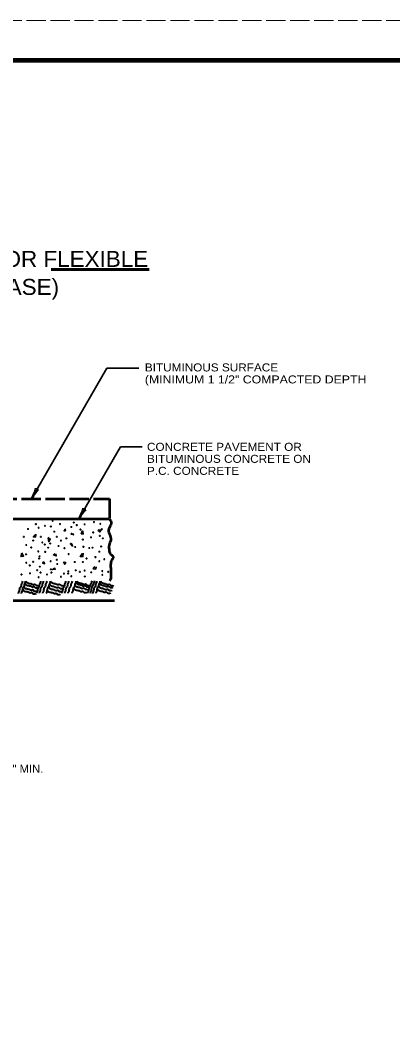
# Model space of a CAD drawing. Extents: x -488 to 193, y 19 to 459.
# Drawn here: x -135 to -41.9, y 203.1 to 458.9 of the extents above; entities that cross this region are included whole.
import ezdxf
from ezdxf.enums import TextEntityAlignment as Align

# ---------------------------------------------------------------- set-up
doc = ezdxf.new("R2010")
doc.units = 0
doc.header["$LTSCALE"] = 0.8
doc.linetypes.add('LONG_DASHED', pattern=[7.5, 6, -1.5])
doc.layers.add('1', color=7, linetype='Continuous', lineweight=40)
doc.layers.add('61', color=7, linetype='Continuous', lineweight=35)

msp = doc.modelspace()

# ---------------------------------------------------------------- linework, layer by layer
at = {"layer": '1', "lineweight": 60}
msp.add_line((-127.368, 396.6702), (-102.8286, 396.6702), dxfattribs=at)
at = {"layer": '1', "lineweight": 35}
for p, q in [((-132.2735, 339.2816), (-113.4017, 371.9683)), ((-113.4017, 371.9683), (-105.4017, 371.9683)), ((-120.4165, 334.2816), (-110.0276, 352.2757)), ((-110.0276, 352.2757), (-104.5276, 352.2757))]:
    msp.add_line(p, q, dxfattribs=at)
at = {"layer": '1', "linetype": 'LONG_DASHED', "lineweight": 53}
for p, q in [((-272.7425, 339.2816), (-112.7425, 339.2816)), ((-112.7425, 339.2816), (-112.7425, 334.2816))]:
    msp.add_line(p, q, dxfattribs=at)
at = {"layer": '1', "lineweight": 53}
for p, q in [((-272.7425, 334.2816), (-112.7425, 334.2816)), ((-271.5283, 313.9212), (-111.5283, 313.9212))]:
    msp.add_line(p, q, dxfattribs=at)
at = {"layer": '1', "lineweight": 35}
for points in [[(-131.3389, 330.2921), (-131.7698, 329.7996), (-131.2774, 329.7381), (-131.1542, 330.4767)], [(-123.7057, 331.7695), (-124.1366, 331.3386), (-123.7672, 331.3386), (-123.8904, 331.7695)], [(-119.4582, 331.4002), (-119.8275, 330.5998), (-119.3351, 330.4767), (-119.3966, 331.277)], [(-115.2722, 331.6463), (-115.58, 331.4002), (-115.1491, 331.0308), (-114.9028, 331.4002), (-115.0875, 331.6463)], [(-128.0763, 329.4918), (-127.9532, 328.5684), (-127.5839, 329.2456), (-128.1379, 329.6765)], [(-122.5977, 328.1375), (-121.9821, 327.4604), (-122.1667, 328.0144), (-122.4745, 328.2607)], [(-134.7247, 325.6752), (-134.8478, 324.8749), (-134.2322, 324.9981), (-134.6632, 325.7983)], [(-126.4142, 325.6752), (-126.7837, 325.3058), (-126.0449, 325.0596), (-126.1681, 325.5521)], [(-119.4582, 325.6752), (-120.0737, 324.8749), (-119.3966, 324.8749), (-119.3351, 325.7367)], [(-129.1844, 323.5822), (-129.4922, 323.2744), (-128.9998, 323.0897), (-129.1228, 323.5207)], [(-124.2597, 323.5207), (-123.9519, 322.9666), (-123.7057, 323.3975), (-124.2597, 323.4591)], [(-116.3802, 322.4126), (-116.8112, 321.797), (-116.1956, 321.7354), (-116.0724, 322.2895)], [(-126.6688, 321.9947), (-127.0382, 321.6253), (-126.2995, 321.6869), (-126.5457, 322.0562)]]:
    msp.add_lwpolyline(points, dxfattribs=at)
for centre in [(-131.1542, 333.0007), (-128.8766, 332.5697), (-127.3992, 332.3851), (-126.9683, 333.8009), (-125.1216, 333.0007), (-121.6743, 333.37), (-120.9356, 332.7544), (-118.9657, 332.9391), (-116.6265, 333.4931), (-115.0259, 333.0623), (-133.1242, 331.7695), (-130.4772, 332.0772), (-126.5374, 331.0923), (-122.2898, 332.2619), (-122.2283, 330.5383), (-121.7974, 330.4152), (-120.0122, 331.6463), (-116.8112, 330.9077), (-115.1491, 330.0458), (-114.6566, 331.7079), (-134.1707, 329.7996), (-133.5551, 327.7682), (-131.8314, 328.8762), (-129.9231, 329.7996), (-129.5538, 328.3837), (-128.9382, 327.8913), (-127.5839, 328.1375), (-125.9218, 329.7996), (-125.4909, 327.5219), (-124.8753, 328.8762), (-123.521, 329.4303), (-121.3049, 327.2758), (-119.3966, 329.1225), (-119.2735, 327.3372), (-117.3652, 329.6765), (-114.8413, 327.3988), (-114.4103, 329.4303), (-133.6167, 325.4289), (-132.3239, 327.1526), (-130.5387, 326.1677), (-130.2309, 324.9365), (-128.8151, 326.0445), (-128.0763, 327.091), (-124.0135, 326.9679), (-122.967, 325.4905), (-117.7961, 327.0295), (-116.9958, 327.091), (-116.2571, 324.7518), (-115.2722, 326.1061), (-133.5551, 323.336), (-132.6933, 322.6588), (-131.8314, 323.5822), (-130.354, 324.3824), (-130.1693, 322.351), (-127.4607, 323.7053), (-125.9218, 324.0747), (-125.7987, 323.0282), (-121.428, 323.5207), (-119.3966, 323.5207), (-118.4732, 324.3824), (-115.2722, 323.7053), (-114.041, 324.1977), (-134.7862, 320.3812), (-132.6317, 320.6889), (-130.8465, 321.4892), (-130.4772, 319.704), (-129.9847, 320.8736), (-128.3842, 320.3812), (-127.3992, 321.6739), (-127.2761, 320.8736), (-124.8753, 319.8272), (-124.1366, 320.6274), (-123.0901, 320.6274), (-123.0286, 321.1814), (-122.2898, 319.9502), (-121.1818, 321.4277), (-120.1353, 321.0583), (-118.9657, 321.3661), (-118.9042, 319.8887), (-117.3036, 320.9352), (-114.5335, 321.243), (-114.5335, 320.3196), (-113.0561, 321.0583)]:
    msp.add_circle(centre, 0.1, dxfattribs=at)
at = {"layer": '1'}
for centre, major_axis, ratio, start_param, end_param in [((-131.9672, 340.3647), (-0.7576, -1.6245), 0.122415, 0.89635335, 3.14159265), ((-131.9672, 340.3647), (-0.7576, -1.6245), 0.122415, 0.89635335, 3.14159265), ((-131.53, 340.1462), (1.0303, 1.4333), 0.07063, 6.28230741, 8.55970261), ((-131.53, 340.1462), (1.0303, 1.4333), 0.07063, 6.28230741, 8.55970261), ((-120.1102, 335.3647), (-0.7576, -1.6245), 0.122415, 0.89635335, 3.14159265), ((-119.673, 335.1462), (-1.0303, -1.4333), 0.07063, 3.14071475, 5.41810995)]:
    msp.add_ellipse(centre, major_axis=major_axis, ratio=ratio, start_param=start_param, end_param=end_param, dxfattribs=at)
at = {"layer": '1', "lineweight": 53}
msp.add_spline([(-112.7425, 334.2816), (-112.2962, 333.2177), (-112.9979, 331.3631), (-112.7472, 330.4608), (-112.4465, 329.0072), (-112.8475, 327.7542), (-112.7974, 326.3006), (-112.647, 325.7492), (-111.845, 324.847), (-112.2962, 323.6941), (-112.4465, 323.1427), (-112.4465, 321.9899), (-112.3964, 320.9874), (-112.4465, 320.1353), (-112.4465, 319.3834), (-112.7425, 318.7816)], degree=3, dxfattribs=at)
at = {"layer": '1'}
for points in [[(-134.5498, 318.7058), (-134.6353, 318.2209), (-134.8207, 317.8786), (-134.9276, 317.2722), (-135.2343, 316.9513), (-135.2556, 316.8302), (-135.3197, 316.4663), (-135.3838, 316.1026), (-135.5693, 315.7603), (-135.5907, 315.639)], [(-133.8112, 318.7058), (-133.8967, 318.2209), (-134.082, 317.8786), (-134.1889, 317.2722), (-134.4957, 316.9513), (-134.5169, 316.8302), (-134.5811, 316.4663), (-134.6452, 316.1026), (-134.8307, 315.7603), (-134.8521, 315.639)], [(-134.2132, 317.3456), (-133.9203, 317.012), (-133.0878, 316.789), (-132.85, 316.7253), (-132.1365, 316.5341), (-131.9857, 316.6212), (-131.5736, 316.2559), (-131.0662, 316.2473), (-130.9791, 316.0966)], [(-133.9054, 318.1458), (-133.6125, 317.8123), (-132.78, 317.5892), (-132.5422, 317.5256), (-131.8287, 317.3343), (-131.6778, 317.4214), (-131.2657, 317.0562), (-130.7583, 317.0475), (-130.6712, 316.8968)], [(-133.6592, 318.6999), (-133.3663, 318.3663), (-132.5337, 318.1433), (-132.2959, 318.0797), (-131.5824, 317.8884), (-131.4316, 317.9755), (-131.0195, 317.6103), (-130.5121, 317.6016), (-130.425, 317.4509)], [(-129.9945, 318.7674), (-130.08, 318.2825), (-130.2653, 317.9402), (-130.3723, 317.3338), (-130.679, 317.0129), (-130.7002, 316.8918), (-130.7644, 316.5279), (-130.8285, 316.1642), (-131.014, 315.8219), (-131.0354, 315.7006)], [(-129.3173, 318.7674), (-129.4028, 318.2825), (-129.5882, 317.9402), (-129.6951, 317.3338), (-130.0018, 317.0129), (-130.0231, 316.8918), (-130.0872, 316.5279), (-130.1513, 316.1642), (-130.3368, 315.8219), (-130.3582, 315.7006)], [(-128.4555, 318.7674), (-128.541, 318.2825), (-128.7263, 317.9402), (-128.8332, 317.3338), (-129.14, 317.0129), (-129.1612, 316.8918), (-129.2254, 316.5279), (-129.2895, 316.1642), (-129.475, 315.8219), (-129.4964, 315.7006)], [(-127.5937, 318.7058), (-127.6792, 318.2209), (-127.8645, 317.8786), (-127.9714, 317.2722), (-128.2782, 316.9513), (-128.2994, 316.8302), (-128.3636, 316.4663), (-128.4277, 316.1026), (-128.6132, 315.7603), (-128.6346, 315.639)], [(-127.9342, 317.2225), (-127.6413, 316.8889), (-126.8088, 316.6659), (-126.571, 316.6022), (-125.8575, 316.411), (-125.7067, 316.4981), (-125.2946, 316.1328), (-124.7872, 316.1242), (-124.7001, 315.9735)], [(-127.7496, 317.9612), (-127.4567, 317.6276), (-126.6242, 317.4046), (-126.3863, 317.3409), (-125.6728, 317.1497), (-125.522, 317.2367), (-125.1099, 316.8715), (-124.6025, 316.8628), (-124.5154, 316.7122)], [(-127.5033, 318.6999), (-127.2104, 318.3663), (-126.3779, 318.1433), (-126.1401, 318.0797), (-125.4266, 317.8884), (-125.2758, 317.9755), (-124.8637, 317.6103), (-124.3563, 317.6016), (-124.2692, 317.4509)], [(-123.7155, 318.7674), (-123.801, 318.2825), (-123.9863, 317.9402), (-124.0932, 317.3338), (-124.4, 317.0129), (-124.4213, 316.8918), (-124.4854, 316.5279), (-124.5495, 316.1642), (-124.735, 315.8219), (-124.7564, 315.7006)], [(-122.9767, 318.7674), (-123.0622, 318.2825), (-123.2476, 317.9402), (-123.3545, 317.3338), (-123.6612, 317.0129), (-123.6825, 316.8918), (-123.7467, 316.5279), (-123.8107, 316.1642), (-123.9962, 315.8219), (-124.0177, 315.7006)], [(-122.1149, 318.7674), (-122.2004, 318.2825), (-122.3858, 317.9402), (-122.4927, 317.3338), (-122.7994, 317.0129), (-122.8207, 316.8918), (-122.8848, 316.5279), (-122.9489, 316.1642), (-123.1344, 315.8219), (-123.1558, 315.7006)], [(-121.13, 318.7674), (-121.2155, 318.2825), (-121.4008, 317.9402), (-121.5078, 317.3338), (-121.8145, 317.0129), (-121.8357, 316.8918), (-121.8999, 316.5279), (-121.964, 316.1642), (-122.1495, 315.8219), (-122.1709, 315.7006)], [(-121.4706, 317.7765), (-121.1777, 317.4429), (-120.3452, 317.2199), (-120.1073, 317.1562), (-119.3938, 316.965), (-119.243, 317.0521), (-118.8309, 316.6868), (-118.3235, 316.6782), (-118.2364, 316.5275)], [(-121.1628, 318.3921), (-120.8699, 318.0585), (-120.0374, 317.8355), (-119.7996, 317.7718), (-119.0861, 317.5806), (-118.9352, 317.6677), (-118.5232, 317.3024), (-118.0157, 317.2937), (-117.9287, 317.1431)], [(-120.9166, 318.7615), (-120.6237, 318.4279), (-119.7912, 318.2049), (-119.5533, 318.1413), (-118.8398, 317.95), (-118.689, 318.0371), (-118.2769, 317.6718), (-117.7695, 317.6632), (-117.6824, 317.5125)], [(-117.1903, 318.829), (-117.2758, 318.3441), (-117.4612, 318.0018), (-117.5681, 317.3954), (-117.8748, 317.0745), (-117.8961, 316.9533), (-117.9603, 316.5895), (-118.0243, 316.2258), (-118.2098, 315.8835), (-118.2313, 315.7622)], [(-116.5747, 318.829), (-116.6602, 318.3441), (-116.8456, 318.0018), (-116.9525, 317.3954), (-117.2592, 317.0745), (-117.2805, 316.9533), (-117.3447, 316.5895), (-117.4087, 316.2258), (-117.5943, 315.8835), (-117.6157, 315.7622)], [(-115.9592, 318.7058), (-116.0447, 318.2209), (-116.23, 317.8786), (-116.3369, 317.2722), (-116.6437, 316.9513), (-116.6649, 316.8302), (-116.7291, 316.4663), (-116.7932, 316.1026), (-116.9787, 315.7603), (-117.0001, 315.639)], [(-115.1589, 318.7674), (-115.2444, 318.2825), (-115.4297, 317.9402), (-115.5367, 317.3338), (-115.8434, 317.0129), (-115.8647, 316.8918), (-115.9288, 316.5279), (-115.9929, 316.1642), (-116.1784, 315.8219), (-116.1998, 315.7006)], [(-115.4378, 317.4688), (-115.1449, 317.1352), (-114.3124, 316.9122), (-114.0746, 316.8485), (-113.3611, 316.6572), (-113.2103, 316.7443), (-112.7982, 316.3791), (-112.2908, 316.3704), (-112.2037, 316.2197)], [(-115.2532, 318.2074), (-114.9603, 317.8738), (-114.1277, 317.6508), (-113.8899, 317.5872), (-113.1764, 317.3959), (-113.0256, 317.483), (-112.6135, 317.1178), (-112.1061, 317.1091), (-112.019, 316.9584)], [(-115.0069, 318.6999), (-114.714, 318.3663), (-113.8815, 318.1433), (-113.6437, 318.0797), (-112.9302, 317.8884), (-112.7793, 317.9755), (-112.3672, 317.6103), (-111.8598, 317.6016), (-111.7728, 317.4509)], [(-134.4595, 316.6684), (-134.1666, 316.3348), (-133.3341, 316.1118), (-133.0962, 316.0482), (-132.3827, 315.8569), (-132.2319, 315.944), (-131.8198, 315.5788), (-131.3124, 315.5701), (-131.2253, 315.4194)], [(-128.3652, 316.4837), (-128.0722, 316.1502), (-127.2398, 315.9272), (-127.0019, 315.8635), (-126.2884, 315.6722), (-126.1376, 315.7593), (-125.7255, 315.3941), (-125.2181, 315.3854), (-125.131, 315.2347)], [(-121.7168, 316.9762), (-121.4239, 316.6427), (-120.5914, 316.4197), (-120.3536, 316.356), (-119.6401, 316.1647), (-119.4892, 316.2518), (-119.0772, 315.8866), (-118.5697, 315.8779), (-118.4827, 315.7272)], [(-115.8072, 316.7916), (-115.5142, 316.458), (-114.6817, 316.235), (-114.4439, 316.1713), (-113.7304, 315.9801), (-113.5796, 316.0672), (-113.1675, 315.7019), (-112.6601, 315.6932), (-112.573, 315.5426)]]:
    msp.add_spline(points, degree=3, dxfattribs=at)
at = {"layer": '61', "linetype": 'LONG_DASHED', "lineweight": 13}
msp.add_line((-487.5027, 458.891), (192.5172, 458.891), dxfattribs=at)
at = {"layer": '61', "lineweight": 158}
msp.add_lwpolyline([(181.5373, 448.891), (-457.5027, 448.891), (-457.5027, 28.871)], dxfattribs=at)

# ---------------------------------------------------------------- texts
at = {"layer": '1', "width": 1.05}
for s, height, p in [('MINIMUM REPLACEMENT REQUIREMENT FOR RIGID OR FLEXIBLE', 4, (-193.2332, 397.283)), ('PAVEMENT CUTS (INCLUDING BASE & SUB-BASE)', 4, (-193.2332, 390.283)), ('18" MIN.', 2, (-134.7218, 270.8227))]:
    msp.add_text(s, height=height, dxfattribs=at).set_placement(p, align=Align.CENTER)
at = {"layer": '1'}
for s, width, p in [('BITUMINOUS SURFACE', 1.1, (-103.8895, 371.1583)), ('(MINIMUM 1 1/2" COMPACTED DEPTH', 1.15, (-103.8895, 368.1583)), ('CONCRETE PAVEMENT OR', 1.1, (-103.3619, 351.3073)), ('BITUMINOUS CONCRETE ON', 1.1, (-103.3619, 348.3073)), ('P.C. CONCRETE', 1.1, (-103.3619, 345.3073))]:
    msp.add_text(s, height=2, dxfattribs=dict(at, width=width)).set_placement(p)

doc.saveas('drawing.dxf')
